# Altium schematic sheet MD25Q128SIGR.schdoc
size 127 x 101 mm
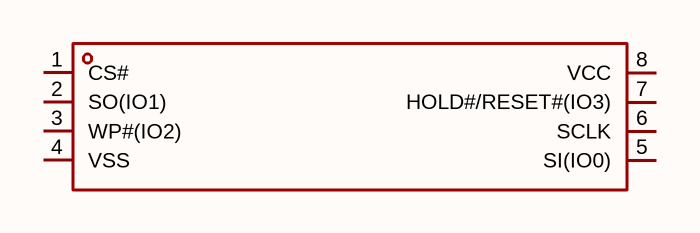
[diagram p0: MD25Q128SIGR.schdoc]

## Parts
U?  md25q128sigr  [SOP-8_L5.3-W5.3-P1.27-LS7.9-BL]  (value not drawn)

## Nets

Not connected (* = marked no-connect by the designer): U? 1(CS#) 2(SO(IO1)) 3(WP#(IO2)) 4(VSS) 5(SI(IO0)) 6(SCLK) 7(HOLD#/RESET#(IO3)) 8(VCC)

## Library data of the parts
U? = md25q128sigr: 接口类型:SPI;存储容量:128Mbit;时钟频率(fc):104MHz;; Manufacturer: GigaDevice(兆易创新); AddInBom: yes; ModelId: 72eaeed142424588879d6a198b07ab72; ModelTransform: 207.67675,311.023,0,0,0,0,0,0,0; Interface: SPI; Clock Frequency: 104MHz; Voltage - Supply: 2.7V~3.6V; Standby Supply Current: 5uA; Program / Erase Cycles: 100000次; Page Programming Time (Tpp): 600us; Block Erase Time(tBE): 300ms; Data Retention - TDR (Year): 20年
